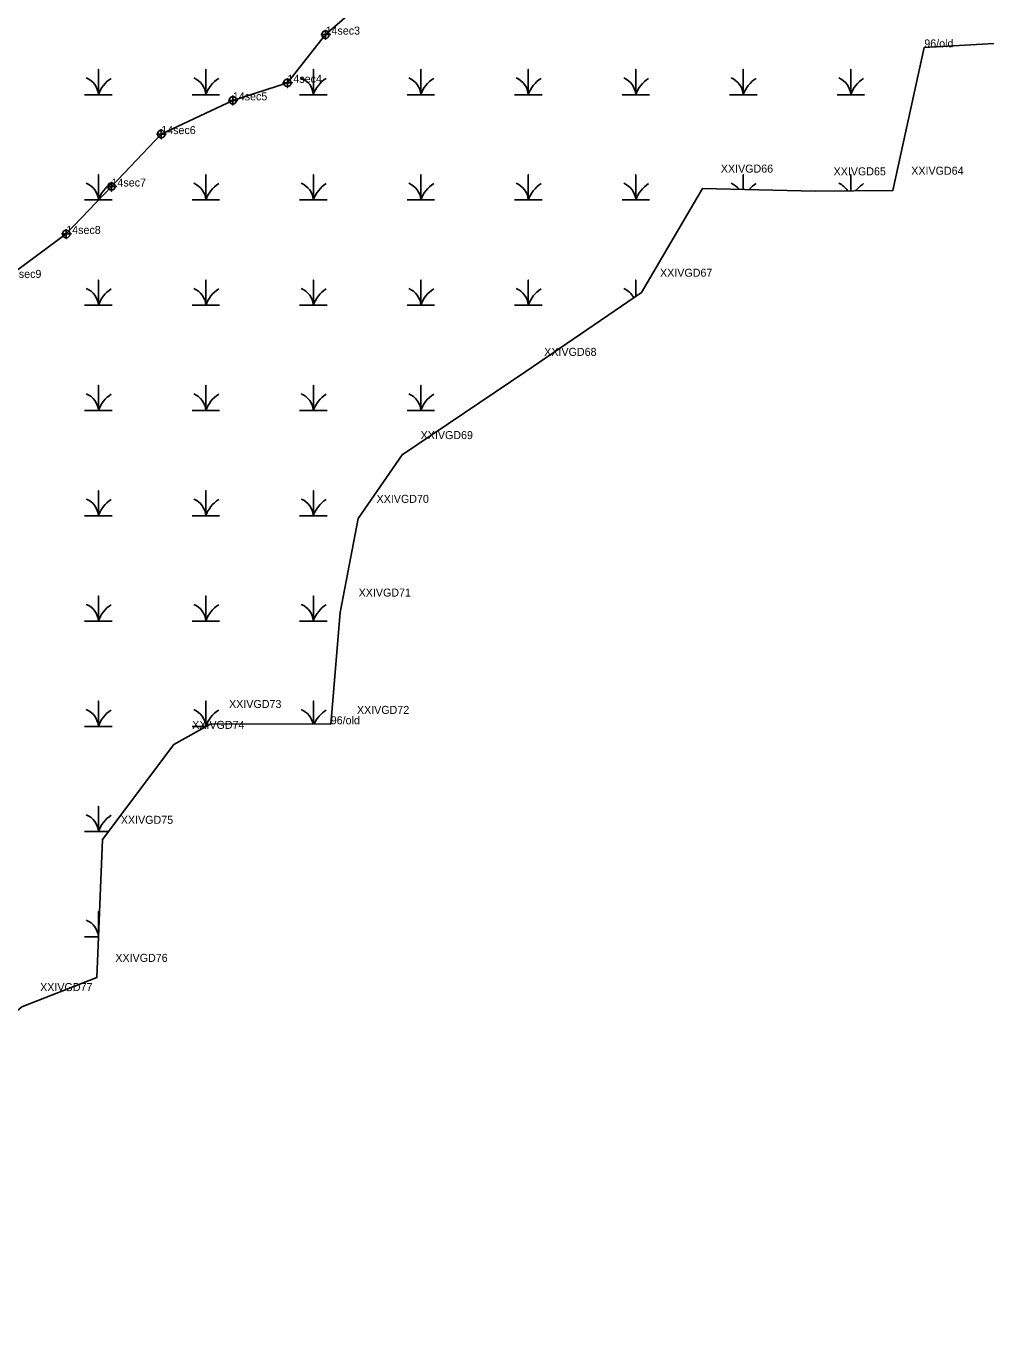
# Model space of a CAD drawing. Extents: x 2071991 to 2268989, y 436479 to 469629.
# Drawn here: x 2263695 to 2264295, y 441828 to 442642 of the extents above; entities that cross this region are included whole.
import ezdxf

# ---------------------------------------------------------------- set-up
doc = ezdxf.new("R2010")
doc.units = 0
for name, color, linetype in [('Exist Environmental Wetland Boundary', 7, 'Continuous'), ('Exist Environmental Wetland Boundary Cogo Comment', 7, 'Continuous'), ('Exist Hydro Jurisdictional Stream or Body of Water NEU Mitigable', 7, 'Continuous'), ('Exist Hydro Jurisdictional Stream or Body of Water NEU Mitigable Cogo Comment', 7, 'Continuous'), ('Exist Hydro Jurisdictional Stream or Body of Water NEU Mitigable Cogo Point CELL', 7, 'Continuous'), ('Exist Hydro Swamp or Marsh', 7, 'Continuous')]:
    doc.layers.add(name, color=color, linetype=linetype)

msp = doc.modelspace()

# ---------------------------------------------------------------- linework, layer by layer
at = {"layer": 'Exist Environmental Wetland Boundary'}
msp.add_lwpolyline([(2264311.19, 442631.38), (2264256.71, 442628.32), (2264237.03, 442538.93), (2264188.47, 442538.55), (2264117.97, 442540.24), (2264079.97, 442475.21), (2264007.54, 442425.75), (2263930.27, 442373.75), (2263902.73, 442333.91), (2263891.51, 442275.34), (2263885.59, 442205.4), (2263810.51, 442205.75), (2263787.43, 442192.68), (2263742.82, 442133.35), (2263739.39, 442047.1), (2263692.37, 442028.85), (2263641.17, 441985.48), (2263606.24, 441900.73), (2263597.49, 441852.35), (2263569.3, 441793.49)], dxfattribs=at)
at = {"layer": 'Exist Hydro Jurisdictional Stream or Body of Water NEU Mitigable'}
msp.add_lwpolyline([(2263924.02, 442672.5), (2263882.33, 442636.32), (2263858.49, 442606.21), (2263824.35, 442595.25), (2263779.6, 442574.16), (2263748.5, 442541.4), (2263720.2, 442511.78), (2263683.1, 442484.3)], dxfattribs=at)
at = {"layer": 'Exist Hydro Jurisdictional Stream or Body of Water NEU Mitigable Cogo Point CELL'}
for points in [[(2263882.33, 442639.32), (2263882.33, 442633.32), (2263882.33, 442636.32), (2263885.33, 442636.32), (2263879.33, 442636.32)], [(2263858.49, 442609.21), (2263858.49, 442603.21), (2263858.49, 442606.21), (2263861.49, 442606.21), (2263855.49, 442606.21)], [(2263824.35, 442598.25), (2263824.35, 442592.25), (2263824.35, 442595.25), (2263827.35, 442595.25), (2263821.35, 442595.25)], [(2263779.6, 442577.16), (2263779.6, 442571.16), (2263779.6, 442574.16), (2263782.6, 442574.16), (2263776.6, 442574.16)], [(2263748.5, 442544.4), (2263748.5, 442538.4), (2263748.5, 442541.4), (2263751.5, 442541.4), (2263745.5, 442541.4)], [(2263720.2, 442514.78), (2263720.2, 442508.78), (2263720.2, 442511.78), (2263723.2, 442511.78), (2263717.2, 442511.78)]]:
    msp.add_lwpolyline(points, dxfattribs=at)
for centre in [(2263882.33, 442636.32), (2263858.49, 442606.21), (2263824.35, 442595.25), (2263779.6, 442574.16), (2263748.5, 442541.4), (2263720.2, 442511.78)]:
    msp.add_circle(centre, 2.34, dxfattribs=at)
at = {"layer": 'Exist Hydro Swamp or Marsh'}
msp.add_line((2264067.72, 442467.21), (2264068.26, 442467.21), dxfattribs=at)
for points in [[(2263731.7, 442598.77), (2263740.3, 442598.77), (2263740.3, 442614.55), (2263740.3, 442598.77), (2263748.91, 442598.77)], [(2263798.91, 442598.77), (2263807.51, 442598.77), (2263807.51, 442614.55), (2263807.51, 442598.77), (2263816.11, 442598.77)], [(2263866.11, 442598.77), (2263874.71, 442598.77), (2263874.71, 442614.55), (2263874.71, 442598.77), (2263883.31, 442598.77)], [(2263933.31, 442598.77), (2263941.91, 442598.77), (2263941.91, 442614.55), (2263941.91, 442598.77), (2263950.52, 442598.77)], [(2264000.52, 442598.77), (2264009.12, 442598.77), (2264009.12, 442614.55), (2264009.12, 442598.77), (2264017.72, 442598.77)], [(2264067.72, 442598.77), (2264076.32, 442598.77), (2264076.32, 442614.55), (2264076.32, 442598.77), (2264084.92, 442598.77)], [(2264134.92, 442598.77), (2264143.52, 442598.77), (2264143.52, 442614.55), (2264143.52, 442598.77), (2264152.13, 442598.77)], [(2264202.13, 442598.77), (2264210.73, 442598.77), (2264210.73, 442614.55), (2264210.73, 442598.77), (2264219.33, 442598.77)], [(2263731.7, 442532.99), (2263740.3, 442532.99), (2263740.3, 442548.77), (2263740.3, 442532.99), (2263748.91, 442532.99)], [(2263798.91, 442532.99), (2263807.51, 442532.99), (2263807.51, 442548.77), (2263807.51, 442532.99), (2263816.11, 442532.99)], [(2263866.11, 442532.99), (2263874.71, 442532.99), (2263874.71, 442548.77), (2263874.71, 442532.99), (2263883.31, 442532.99)], [(2263933.31, 442532.99), (2263941.91, 442532.99), (2263941.91, 442548.77), (2263941.91, 442532.99), (2263950.52, 442532.99)], [(2264000.52, 442532.99), (2264009.12, 442532.99), (2264009.12, 442548.77), (2264009.12, 442532.99), (2264017.72, 442532.99)], [(2264067.72, 442532.99), (2264076.32, 442532.99), (2264076.32, 442548.77), (2264076.32, 442532.99), (2264084.92, 442532.99)], [(2264143.52, 442539.63), (2264143.52, 442548.77), (2264143.52, 442539.63)], [(2264210.73, 442538.73), (2264210.73, 442548.77), (2264210.73, 442538.73)], [(2263731.7, 442467.21), (2263740.3, 442467.21), (2263740.3, 442482.99), (2263740.3, 442467.21), (2263748.91, 442467.21)], [(2263798.91, 442467.21), (2263807.51, 442467.21), (2263807.51, 442482.99), (2263807.51, 442467.21), (2263816.11, 442467.21)], [(2263866.11, 442467.21), (2263874.71, 442467.21), (2263874.71, 442482.99), (2263874.71, 442467.21), (2263883.31, 442467.21)], [(2263933.31, 442467.21), (2263941.91, 442467.21), (2263941.91, 442482.99), (2263941.91, 442467.21), (2263950.52, 442467.21)], [(2264000.52, 442467.21), (2264009.12, 442467.21), (2264009.12, 442482.99), (2264009.12, 442467.21), (2264017.72, 442467.21)], [(2264076.32, 442472.71), (2264076.32, 442482.99), (2264076.32, 442472.71)], [(2263731.7, 442401.43), (2263740.3, 442401.43), (2263740.3, 442417.21), (2263740.3, 442401.43), (2263748.91, 442401.43)], [(2263798.91, 442401.43), (2263807.51, 442401.43), (2263807.51, 442417.21), (2263807.51, 442401.43), (2263816.11, 442401.43)], [(2263866.11, 442401.43), (2263874.71, 442401.43), (2263874.71, 442417.21), (2263874.71, 442401.43), (2263883.31, 442401.43)], [(2263933.31, 442401.43), (2263941.91, 442401.43), (2263941.91, 442417.21), (2263941.91, 442401.43), (2263950.52, 442401.43)], [(2263731.7, 442335.65), (2263740.3, 442335.65), (2263740.3, 442351.43), (2263740.3, 442335.65), (2263748.91, 442335.65)], [(2263798.91, 442335.65), (2263807.51, 442335.65), (2263807.51, 442351.43), (2263807.51, 442335.65), (2263816.11, 442335.65)], [(2263866.11, 442335.65), (2263874.71, 442335.65), (2263874.71, 442351.43), (2263874.71, 442335.65), (2263883.31, 442335.65)], [(2263731.7, 442269.87), (2263740.3, 442269.87), (2263740.3, 442285.65), (2263740.3, 442269.87), (2263748.91, 442269.87)], [(2263798.91, 442269.87), (2263807.51, 442269.87), (2263807.51, 442285.65), (2263807.51, 442269.87), (2263816.11, 442269.87)], [(2263866.11, 442269.87), (2263874.71, 442269.87), (2263874.71, 442285.65), (2263874.71, 442269.87), (2263883.31, 442269.87)], [(2263731.7, 442204.09), (2263740.3, 442204.09), (2263740.3, 442219.87), (2263740.3, 442204.09), (2263748.91, 442204.09)], [(2263798.91, 442204.09), (2263807.51, 442204.09), (2263807.51, 442219.87), (2263807.51, 442204.09), (2263807.59, 442204.09)], [(2263874.71, 442205.45), (2263874.71, 442219.87), (2263874.71, 442205.45)], [(2263731.7, 442138.31), (2263740.3, 442138.31), (2263740.3, 442154.09), (2263740.3, 442138.31), (2263746.55, 442138.31)], [(2263731.7, 442072.53), (2263740.3, 442072.53), (2263740.3, 442088.31), (2263740.3, 442072.53), (2263740.4, 442072.53)]]:
    msp.add_lwpolyline(points, dxfattribs=at)
for centre, radius, start, end in [((2263728.04, 442597.88), 12.3, 4.14034, 67.53497), ((2263758.55, 442592.71), 19.22, 122.12745, 161.62219), ((2263795.24, 442597.88), 12.3, 4.14034, 67.53497), ((2263825.75, 442592.71), 19.22, 122.12745, 161.62219), ((2263862.44, 442597.88), 12.3, 4.14034, 67.53497), ((2263892.95, 442592.71), 19.22, 122.12745, 161.62219), ((2263929.65, 442597.88), 12.3, 4.14034, 67.53497), ((2263960.16, 442592.71), 19.22, 122.12745, 161.62219), ((2263996.85, 442597.88), 12.3, 4.14034, 67.53497), ((2264027.36, 442592.71), 19.22, 122.12745, 161.62219), ((2264064.05, 442597.88), 12.3, 4.14034, 67.53497), ((2264094.56, 442592.71), 19.22, 122.12745, 161.62219), ((2264131.26, 442597.88), 12.3, 4.14034, 67.53497), ((2264161.77, 442592.71), 19.22, 122.12745, 161.62219), ((2264198.46, 442597.88), 12.3, 4.14034, 67.53497), ((2264228.97, 442592.71), 19.22, 122.12745, 161.62219), ((2263728.04, 442532.1), 12.3, 4.14034, 67.53497), ((2263758.55, 442526.93), 19.22, 122.12745, 161.62219), ((2263795.24, 442532.1), 12.3, 4.14034, 67.53497), ((2263825.75, 442526.93), 19.22, 122.12745, 161.62219), ((2263862.44, 442532.1), 12.3, 4.14034, 67.53497), ((2263892.95, 442526.93), 19.22, 122.12745, 161.62219), ((2263929.65, 442532.1), 12.3, 4.14034, 67.53497), ((2263960.16, 442526.93), 19.22, 122.12745, 161.62219), ((2263996.85, 442532.1), 12.3, 4.14034, 67.53497), ((2264027.36, 442526.93), 19.22, 122.12745, 161.62219), ((2264064.05, 442532.1), 12.3, 4.14034, 67.53497), ((2264094.56, 442526.93), 19.22, 122.12745, 161.62219), ((2264131.26, 442532.1), 12.3, 38.10206, 67.53497), ((2264161.77, 442526.93), 19.22, 122.12745, 139.00586), ((2264198.46, 442532.1), 12.3, 32.5027, 67.53497), ((2264228.97, 442526.93), 19.22, 122.12745, 142.05388), ((2263728.04, 442466.32), 12.3, 4.14034, 67.53497), ((2263758.55, 442461.15), 19.22, 122.12745, 161.62219), ((2263795.24, 442466.32), 12.3, 4.14034, 67.53497), ((2263825.75, 442461.15), 19.22, 122.12745, 161.62219), ((2263862.44, 442466.32), 12.3, 4.14034, 67.53497), ((2263892.95, 442461.15), 19.22, 122.12745, 161.62219), ((2263929.65, 442466.32), 12.3, 4.14034, 67.53497), ((2263960.16, 442461.15), 19.22, 122.12745, 161.62219), ((2263996.85, 442466.32), 12.3, 4.14034, 67.53497), ((2264027.36, 442461.15), 19.22, 122.12745, 161.62219), ((2264064.05, 442466.32), 12.3, 26.66662, 67.53497), ((2263728.04, 442400.54), 12.3, 4.14034, 67.53497), ((2263758.55, 442395.37), 19.22, 122.12745, 161.62219), ((2263795.24, 442400.54), 12.3, 4.14034, 67.53497), ((2263825.75, 442395.37), 19.22, 122.12745, 161.62219), ((2263862.44, 442400.54), 12.3, 4.14034, 67.53497), ((2263892.95, 442395.37), 19.22, 122.12745, 161.62219), ((2263929.65, 442400.54), 12.3, 4.14034, 67.53497), ((2263960.16, 442395.37), 19.22, 122.12745, 161.62219), ((2263728.04, 442334.76), 12.3, 4.14034, 67.53497), ((2263758.55, 442329.59), 19.22, 122.12745, 161.62219), ((2263795.24, 442334.76), 12.3, 4.14034, 67.53497), ((2263825.75, 442329.59), 19.22, 122.12745, 161.62219), ((2263862.44, 442334.76), 12.3, 4.14034, 67.53497), ((2263892.95, 442329.59), 19.22, 122.12745, 161.62219), ((2263728.04, 442268.98), 12.3, 4.14034, 67.53497), ((2263795.24, 442268.98), 12.3, 4.14034, 67.53497), ((2263862.44, 442268.98), 12.3, 4.14034, 67.53497), ((2263758.55, 442263.81), 19.22, 122.12745, 161.62219), ((2263825.75, 442263.81), 19.22, 122.12745, 161.62219), ((2263892.95, 442263.81), 19.22, 122.12745, 161.62219), ((2263728.04, 442203.2), 12.3, 4.14034, 67.53497), ((2263758.55, 442198.03), 19.22, 122.12745, 161.62219), ((2263795.24, 442203.2), 12.3, 4.14034, 67.53497), ((2263825.75, 442198.03), 19.22, 122.12745, 161.62219), ((2263862.44, 442203.2), 12.3, 10.52302, 67.53497), ((2263892.95, 442198.03), 19.22, 122.12745, 157.3086), ((2263728.04, 442137.42), 12.3, 4.14034, 67.53497), ((2263758.55, 442132.25), 19.22, 122.12745, 161.62219), ((2263728.04, 442071.64), 12.3, 4.14034, 67.53497), ((2263758.55, 442066.47), 19.22, 160.57948, 161.62219)]:
    msp.add_arc(centre, radius, start, end, dxfattribs=at)

# ---------------------------------------------------------------- texts
at = {"layer": 'Exist Environmental Wetland Boundary Cogo Comment'}
for s, p in [('96/old', (2264256.71, 442628.32)), ('XXIVGD66 ', (2264129.48, 442550.09)), ('XXIVGD65 ', (2264199.98, 442548.39)), ('XXIVGD64 ', (2264248.54, 442548.78)), ('XXIVGD67 ', (2264091.48, 442485.05)), ('XXIVGD68 ', (2264019.05, 442435.59)), ('XXIVGD69 ', (2263941.78, 442383.59)), ('XXIVGD70 ', (2263914.24, 442343.75)), ('XXIVGD71 ', (2263903.02, 442285.18)), ('XXIVGD73 ', (2263822.02, 442215.59)), ('XXIVGD72 ', (2263901.95, 442211.89)), ('XXIVGD74 ', (2263798.94, 442202.52)), ('96/old', (2263885.59, 442205.4)), ('XXIVGD75 ', (2263754.33, 442143.2)), ('XXIVGD76 ', (2263750.9, 442056.95)), ('XXIVGD77 ', (2263703.88, 442038.69))]:
    msp.add_text(s, height=5, dxfattribs=at).set_placement(p)
at = {"layer": 'Exist Hydro Jurisdictional Stream or Body of Water NEU Mitigable Cogo Comment'}
for s, p in [('14sec3', (2263882.33, 442636.32)), ('14sec4', (2263858.49, 442606.21)), ('14sec5', (2263824.35, 442595.25)), ('14sec6', (2263779.6, 442574.16)), ('14sec7', (2263748.5, 442541.4)), ('14sec8', (2263720.2, 442511.78)), ('14sec9', (2263683.1, 442484.3))]:
    msp.add_text(s, height=5, dxfattribs=at).set_placement(p)

doc.saveas('drawing.dxf')
